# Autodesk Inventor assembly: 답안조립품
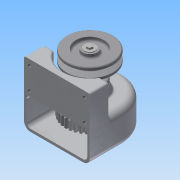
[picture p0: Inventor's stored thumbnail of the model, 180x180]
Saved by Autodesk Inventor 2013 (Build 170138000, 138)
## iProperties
Created: 2015-02
Part Number: 답안조립품
Document SubType Name: Assembly
Designer: Administrator
Author: Administrator
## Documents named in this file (14)
- C:\Documents and Settings\Administrator\바탕 화면\450214V1005\답안조립품.iam
- C:\Documents and Settings\Administrator\바탕 화면\450214V1005\1-본체.ipt
- C:\Documents and Settings\Administrator\바탕 화면\450214V1005\베어링 6001.ipt
- C:\Documents and Settings\Administrator\바탕 화면\450214V1005\축커버.ipt
- C:\Documents and Settings\Administrator\바탕 화면\450214V1005\오일실.ipt
- C:\Documents and Settings\Administrator\바탕 화면\450214V1005\축.ipt
- C:\Documents and Settings\Administrator\바탕 화면\450214V1005\키5x5.ipt
- C:\Documents and Settings\Administrator\바탕 화면\450214V1005\5-스퍼기어.ipt
- C:\Documents and Settings\Administrator\바탕 화면\450214V1005\M3x0.5.ipt
- C:\Documents and Settings\Administrator\바탕 화면\450214V1005\키4x4.ipt
- C:\Documents and Settings\Administrator\바탕 화면\450214V1005\4-벨트풀리.ipt
- C:\Documents and Settings\Administrator\바탕 화면\450214V1005\M5x0.8.ipt
- M5x0.8.ipt
- C:\Documents and Settings\Administrator\바탕 화면\450214V1005\와샤.ipt
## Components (7 placed, 4 different names)
1. 1-본체:1
2. 4-벨트풀리:1 — 각도:4, 각도:5
3. M5x0.8:1 — 각도:5
4. M3x0.5:1
5. M3x0.5:2
6. M3x0.5:3
7. M3x0.5:4
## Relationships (2: Angle 2)
- 각도:4 [Angle]: 4-벨트풀리:1
- 각도:5 [Angle]: 4-벨트풀리:1 ↔ M5x0.8:1
